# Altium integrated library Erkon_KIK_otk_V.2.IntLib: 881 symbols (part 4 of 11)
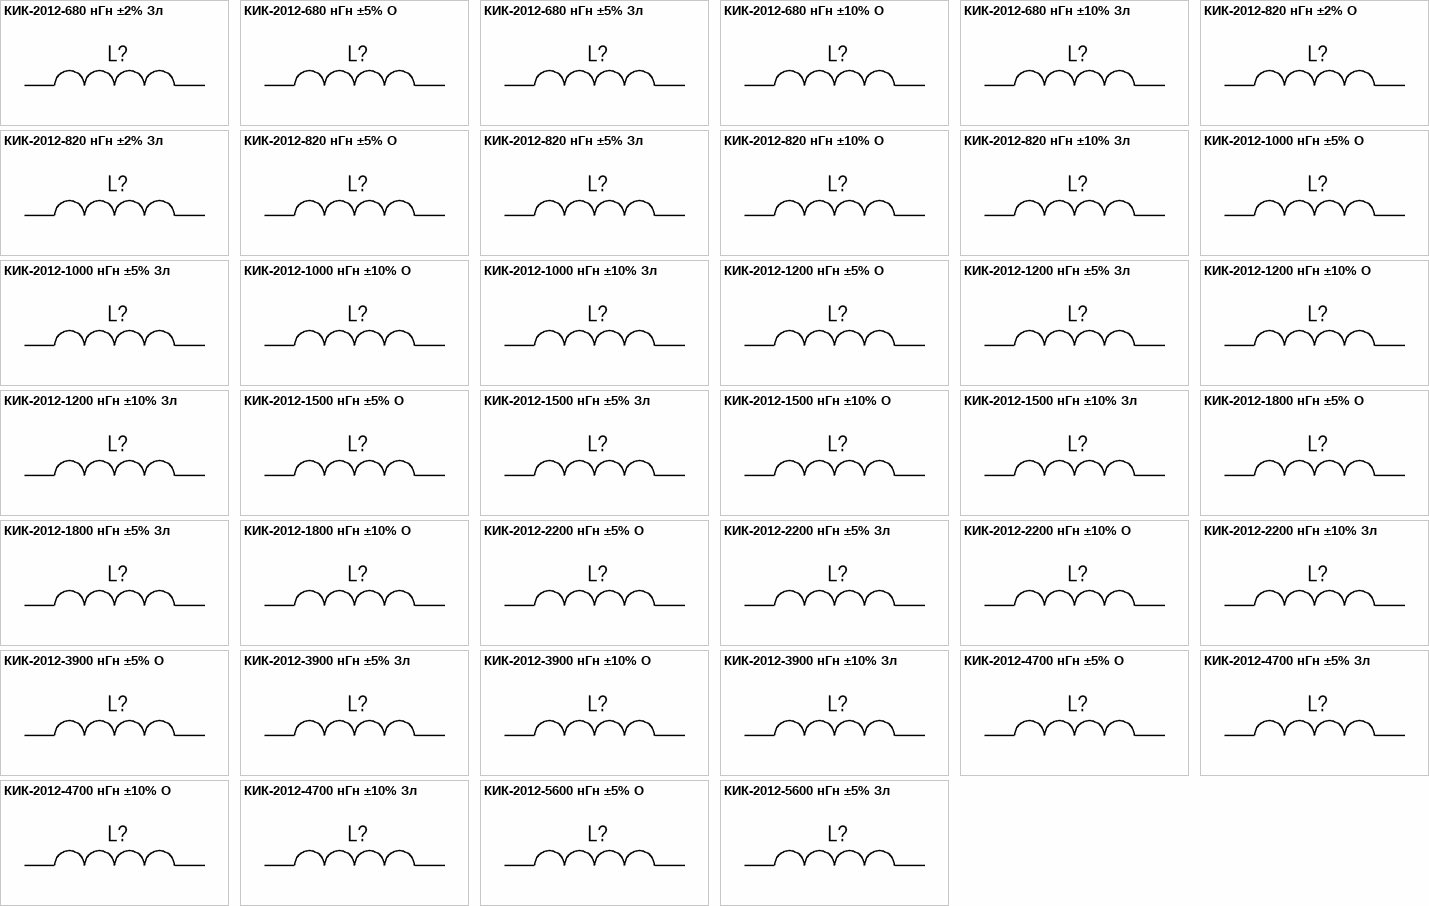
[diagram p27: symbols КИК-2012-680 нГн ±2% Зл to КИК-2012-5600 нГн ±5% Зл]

## КИК-2012-5600 нГн ±5% O
designator L?, comment 5600 нГн ±5%  (value not drawn)
Катушка индуктивности с керамическим сердечником и  финишным покрытием контактных площадок оловом; Добротность, не менее: 17; Резонансная частота, не менее: 0.065 ГГц; Сопротивление обмотки постоянноми току, не более: 7.8 Ом; Допустимый ток обмотки: 50 мА; Диапазон рабочих температур: от -60 до +125 ℃; Упаковка: Катушка и лента; Типоразмер: 2012 (0805); Технология монтажа: SMT; Изготовитель: АО "НПО "ЭРКОН"
footprint КИК-2012-O (Катушка индуктивности с керамическим сердечником типоразмер 2012(0805))
pins: 1, 2

## КИК-2012-5600 нГн ±5% Зл
designator L?, comment 5600 нГн ±5%  (value not drawn)
Катушка индуктивности с керамическим сердечником и золотым покрытием контактных площадок; Добротность, не менее: 17; Резонансная частота, не менее: 0.065 ГГц; Сопротивление обмотки постоянноми току, не более: 7.8 Ом; Допустимый ток обмотки: 50 мА; Диапазон рабочих температур: от -60 до +125 ℃; Упаковка: Катушка и лента; Типоразмер: 2012 (0805); Технология монтажа: SMT; Изготовитель: АО "НПО "ЭРКОН"
footprint КИК-2012-Зл (Катушка индуктивности с керамическим сердечникомтипоразмер 2012(0805))
pins: 1, 2

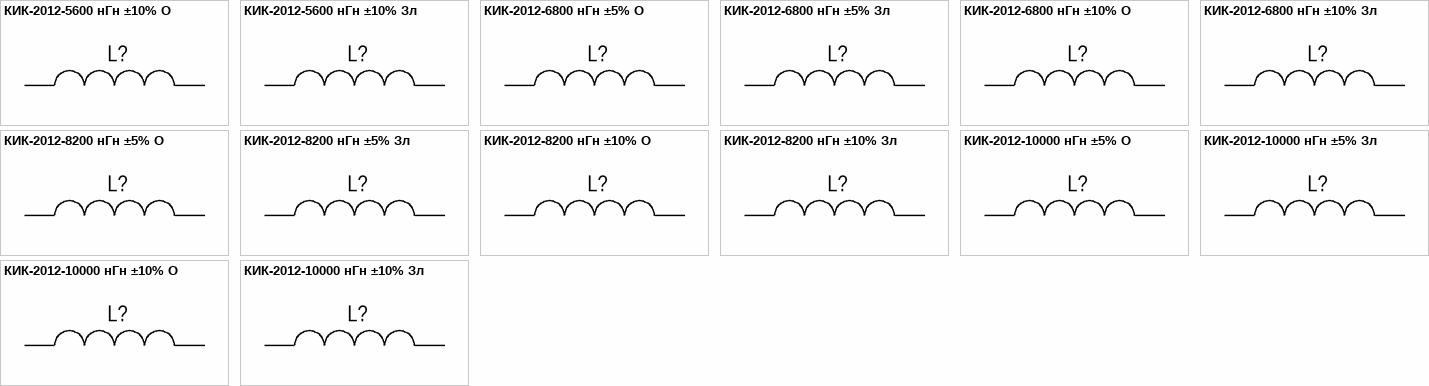
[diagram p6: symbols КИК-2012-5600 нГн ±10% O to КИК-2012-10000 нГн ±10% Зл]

## КИК-2012-5600 нГн ±10% O
designator L?, comment 5600 нГн ±10%  (value not drawn)
Катушка индуктивности с керамическим сердечником и  финишным покрытием контактных площадок оловом; Допускаемое отклонение индуктивности: ±5%; Добротность, не менее: 17; Резонансная частота, не менее: 0.065 ГГц; Сопротивление обмотки постоянноми току, не более: 7.8 Ом; Допустимый ток обмотки: 50 мА; Диапазон рабочих температур: от -60 до +125 ℃; Упаковка: Катушка и лента; Типоразмер: 2012 (0805); Технология монтажа: SMT; Изготовитель: АО "НПО "ЭРКОН"
footprint КИК-2012-O (Катушка индуктивности с керамическим сердечником типоразмер 2012(0805))
pins: 1, 2

## КИК-2012-5600 нГн ±10% Зл
designator L?, comment 5600 нГн ±10%  (value not drawn)
Катушка индуктивности с керамическим сердечником и золотым покрытием контактных площадок; Допускаемое отклонение индуктивности: ±5%; Добротность, не менее: 17; Резонансная частота, не менее: 0.065 ГГц; Сопротивление обмотки постоянноми току, не более: 7.8 Ом; Допустимый ток обмотки: 50 мА; Диапазон рабочих температур: от -60 до +125 ℃; Упаковка: Катушка и лента; Типоразмер: 2012 (0805); Технология монтажа: SMT; Изготовитель: АО "НПО "ЭРКОН"
footprint КИК-2012-Зл (Катушка индуктивности с керамическим сердечникомтипоразмер 2012(0805))
pins: 1, 2

## КИК-2012-6800 нГн ±5% O
designator L?, comment 6800 нГн ±5%  (value not drawn)
Катушка индуктивности с керамическим сердечником и  финишным покрытием контактных площадок оловом; Добротность, не менее: 17; Резонансная частота, не менее: 0.05 ГГц; Сопротивление обмотки постоянноми току, не более: 8.5 Ом; Допустимый ток обмотки: 45 мА; Диапазон рабочих температур: от -60 до +125 ℃; Упаковка: Катушка и лента; Типоразмер: 2012 (0805); Технология монтажа: SMT; Изготовитель: АО "НПО "ЭРКОН"
footprint КИК-2012-O (Катушка индуктивности с керамическим сердечником типоразмер 2012(0805))
pins: 1, 2

## КИК-2012-6800 нГн ±5% Зл
designator L?, comment 6800 нГн ±5%  (value not drawn)
Катушка индуктивности с керамическим сердечником и золотым покрытием контактных площадок; Добротность, не менее: 17; Резонансная частота, не менее: 0.05 ГГц; Сопротивление обмотки постоянноми току, не более: 8.5 Ом; Допустимый ток обмотки: 45 мА; Диапазон рабочих температур: от -60 до +125 ℃; Упаковка: Катушка и лента; Типоразмер: 2012 (0805); Технология монтажа: SMT; Изготовитель: АО "НПО "ЭРКОН"
footprint КИК-2012-Зл (Катушка индуктивности с керамическим сердечникомтипоразмер 2012(0805))
pins: 1, 2

## КИК-2012-6800 нГн ±10% O
designator L?, comment 6800 нГн ±10%  (value not drawn)
Катушка индуктивности с керамическим сердечником и  финишным покрытием контактных площадок оловом; Добротность, не менее: 17; Резонансная частота, не менее: 0.05 ГГц; Сопротивление обмотки постоянноми току, не более: 8.5 Ом; Допустимый ток обмотки: 45 мА; Диапазон рабочих температур: от -60 до +125 ℃; Упаковка: Катушка и лента; Типоразмер: 2012 (0805); Технология монтажа: SMT; Изготовитель: АО "НПО "ЭРКОН"
footprint КИК-2012-O (Катушка индуктивности с керамическим сердечником типоразмер 2012(0805))
pins: 1, 2

## КИК-2012-6800 нГн ±10% Зл
designator L?, comment 6800 нГн ±10%  (value not drawn)
Катушка индуктивности с керамическим сердечником и золотым покрытием контактных площадок; Добротность, не менее: 17; Резонансная частота, не менее: 0.05 ГГц; Сопротивление обмотки постоянноми току, не более: 8.5 Ом; Допустимый ток обмотки: 45 мА; Диапазон рабочих температур: от -60 до +125 ℃; Упаковка: Катушка и лента; Типоразмер: 2012 (0805); Технология монтажа: SMT; Изготовитель: АО "НПО "ЭРКОН"
footprint КИК-2012-Зл (Катушка индуктивности с керамическим сердечникомтипоразмер 2012(0805))
pins: 1, 2

## КИК-2012-8200 нГн ±5% O
designator L?, comment 8200 нГн ±5%  (value not drawn)
Катушка индуктивности с керамическим сердечником и  финишным покрытием контактных площадок оловом; Добротность, не менее: 17; Резонансная частота, не менее: 0.055 ГГц; Сопротивление обмотки постоянноми току, не более: 10.0 Ом; Допустимый ток обмотки: 40 мА; Диапазон рабочих температур: от -60 до +125 ℃; Упаковка: Катушка и лента; Типоразмер: 2012 (0805); Технология монтажа: SMT; Изготовитель: АО "НПО "ЭРКОН"
footprint КИК-2012-O (Катушка индуктивности с керамическим сердечником типоразмер 2012(0805))
pins: 1, 2

## КИК-2012-8200 нГн ±5% Зл
designator L?, comment 8200 нГн ±5%  (value not drawn)
Катушка индуктивности с керамическим сердечником и золотым покрытием контактных площадок; Добротность, не менее: 17; Резонансная частота, не менее: 0.055 ГГц; Сопротивление обмотки постоянноми току, не более: 10.0 Ом; Допустимый ток обмотки: 40 мА; Диапазон рабочих температур: от -60 до +125 ℃; Упаковка: Катушка и лента; Типоразмер: 2012 (0805); Технология монтажа: SMT; Изготовитель: АО "НПО "ЭРКОН"
footprint КИК-2012-Зл (Катушка индуктивности с керамическим сердечникомтипоразмер 2012(0805))
pins: 1, 2

## КИК-2012-8200 нГн ±10% O
designator L?, comment 8200 нГн ±10%  (value not drawn)
Катушка индуктивности с керамическим сердечником и  финишным покрытием контактных площадок оловом; Добротность, не менее: 17; Резонансная частота, не менее: 0.055 ГГц; Сопротивление обмотки постоянноми току, не более: 10.0 Ом; Допустимый ток обмотки: 40 мА; Диапазон рабочих температур: от -60 до +125 ℃; Упаковка: Катушка и лента; Типоразмер: 2012 (0805); Технология монтажа: SMT; Изготовитель: АО "НПО "ЭРКОН"
footprint КИК-2012-O (Катушка индуктивности с керамическим сердечником типоразмер 2012(0805))
pins: 1, 2

## КИК-2012-8200 нГн ±10% Зл
designator L?, comment 8200 нГн ±10%  (value not drawn)
Катушка индуктивности с керамическим сердечником и золотым покрытием контактных площадок; Добротность, не менее: 17; Резонансная частота, не менее: 0.055 ГГц; Сопротивление обмотки постоянноми току, не более: 10.0 Ом; Допустимый ток обмотки: 40 мА; Диапазон рабочих температур: от -60 до +125 ℃; Упаковка: Катушка и лента; Типоразмер: 2012 (0805); Технология монтажа: SMT; Изготовитель: АО "НПО "ЭРКОН"
footprint КИК-2012-Зл (Катушка индуктивности с керамическим сердечникомтипоразмер 2012(0805))
pins: 1, 2

## КИК-2012-10000 нГн ±5% O
designator L?, comment 10000 нГн ±5%  (value not drawn)
Катушка индуктивности с керамическим сердечником и  финишным покрытием контактных площадок оловом; Добротность, не менее: 17; Резонансная частота, не менее: 0.05 ГГц; Сопротивление обмотки постоянноми току, не более: 17.0 Ом; Допустимый ток обмотки: 40 мА; Диапазон рабочих температур: от -60 до +125 ℃; Упаковка: Катушка и лента; Типоразмер: 2012 (0805); Технология монтажа: SMT; Изготовитель: АО "НПО "ЭРКОН"
footprint КИК-2012-O (Катушка индуктивности с керамическим сердечником типоразмер 2012(0805))
pins: 1, 2

## КИК-2012-10000 нГн ±5% Зл
designator L?, comment 10000 нГн ±5%  (value not drawn)
Катушка индуктивности с керамическим сердечником и золотым покрытием контактных площадок; Добротность, не менее: 17; Резонансная частота, не менее: 0.05 ГГц; Сопротивление обмотки постоянноми току, не более: 17.0 Ом; Допустимый ток обмотки: 40 мА; Диапазон рабочих температур: от -60 до +125 ℃; Упаковка: Катушка и лента; Типоразмер: 2012 (0805); Технология монтажа: SMT; Изготовитель: АО "НПО "ЭРКОН"
footprint КИК-2012-Зл (Катушка индуктивности с керамическим сердечникомтипоразмер 2012(0805))
pins: 1, 2

## КИК-2012-10000 нГн ±10% O
designator L?, comment 10000 нГн ±10%  (value not drawn)
Катушка индуктивности с керамическим сердечником и  финишным покрытием контактных площадок оловом; Добротность, не менее: 17; Резонансная частота, не менее: 0.05 ГГц; Сопротивление обмотки постоянноми току, не более: 17.0 Ом; Допустимый ток обмотки: 40 мА; Диапазон рабочих температур: от -60 до +125 ℃; Упаковка: Катушка и лента; Типоразмер: 2012 (0805); Технология монтажа: SMT; Изготовитель: АО "НПО "ЭРКОН"
footprint КИК-2012-O (Катушка индуктивности с керамическим сердечником типоразмер 2012(0805))
pins: 1, 2

## КИК-2012-10000 нГн ±10% Зл
designator L?, comment 10000 нГн ±10%  (value not drawn)
Катушка индуктивности с керамическим сердечником и золотым покрытием контактных площадок; Добротность, не менее: 17; Резонансная частота, не менее: 0.05 ГГц; Сопротивление обмотки постоянноми току, не более: 17.0 Ом; Допустимый ток обмотки: 40 мА; Диапазон рабочих температур: от -60 до +125 ℃; Упаковка: Катушка и лента; Типоразмер: 2012 (0805); Технология монтажа: SMT; Изготовитель: АО "НПО "ЭРКОН"
footprint КИК-2012-Зл (Катушка индуктивности с керамическим сердечникомтипоразмер 2012(0805))
pins: 1, 2


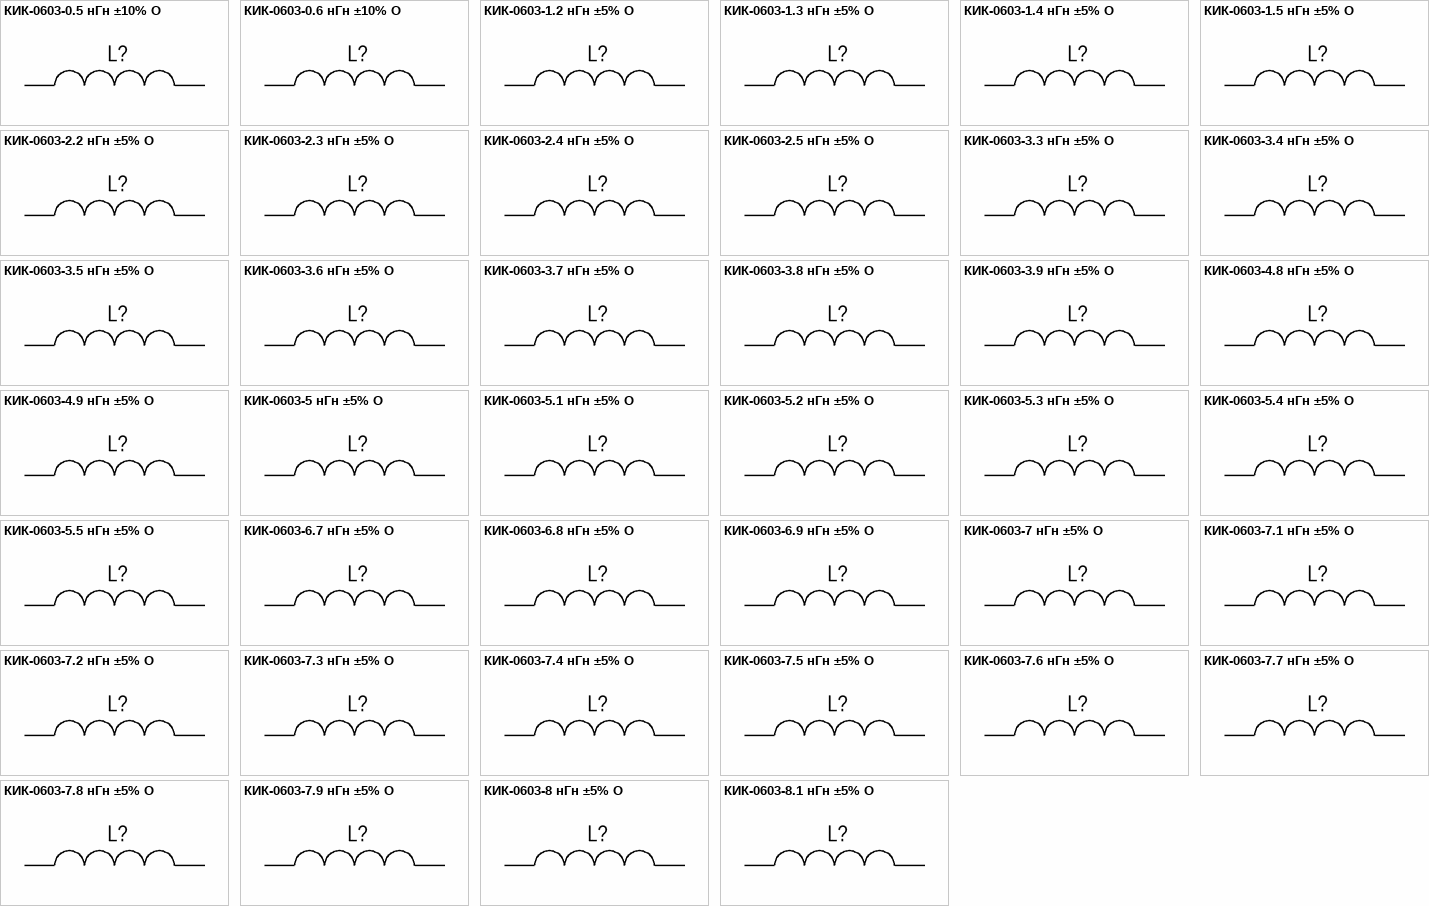
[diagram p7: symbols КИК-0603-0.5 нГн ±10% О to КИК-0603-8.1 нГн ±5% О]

## КИК-0603-0.5 нГн ±10% О
designator L?, comment 0.5нГн ±10%  (value not drawn)
Катушка индуктивности с керамическим сердечником; Добротность, не менее: 29; Резонансная частота, не менее: 23.5 ГГц; Сопротивление обмотки постоянноми току, не более: 0.02 Ом; Допустимый ток обмотки: 1250 мА; Диапазон рабочих температур: от -40 до +125 ℃; Упаковка: Катушка и лента; Типоразмер: 0603 (0201); Технология монтажа: SMT; Изготовитель: АО "НПО "ЭРКОН"
footprint КИК-0603_О (Катушка индуктивности с керамическим сердечником типоразмер 0603(0201))
pins: 1, 2

## КИК-0603-0.6 нГн ±10% О
designator L?, comment 0.6 нГн ±10%  (value not drawn)
Катушка индуктивности с керамическим сердечником; Номиналиная индуктивность: 0.6 нГн; Добротность, не менее: 31; Резонансная частота, не менее: 24.5 ГГц; Сопротивление обмотки постоянноми току, не более: 0.03 Ом; Допустимый ток обмотки: 1000 мА; Диапазон рабочих температур: от -40 до +125 ℃; Упаковка: Катушка и лента; Типоразмер: 0603 (0201); Технология монтажа: SMT; Изготовитель: АО "НПО "ЭРКОН"
footprint КИК-0603_О (Катушка индуктивности с керамическим сердечником типоразмер 0603(0201))
pins: 1, 2

## КИК-0603-1.2 нГн ±5% О
designator L?, comment 1.2 нГн ±5%  (value not drawn)
Катушка индуктивности с керамическим сердечником; Номиналиная индуктивность: 1.2 нГн; Добротность, не менее: 42; Резонансная частота, не менее: 17.9 ГГц; Сопротивление обмотки постоянноми току, не более: 0.042 Ом; Допустимый ток обмотки: 870 мА; Диапазон рабочих температур: от -40 до +125 ℃; Упаковка: Катушка и лента; Типоразмер: 0603 (0201); Технология монтажа: SMT; Изготовитель: АО "НПО "ЭРКОН"
footprint КИК-0603_О (Катушка индуктивности с керамическим сердечником типоразмер 0603(0201))
pins: 1, 2

## КИК-0603-1.3 нГн ±5% О
designator L?, comment 1.3 нГн ±5%  (value not drawn)
Катушка индуктивности с керамическим сердечником; Номиналиная индуктивность: 1.3 нГн; Добротность, не менее: 38; Резонансная частота, не менее: 17.6 ГГц; Сопротивление обмотки постоянноми току, не более: 0.048 Ом; Допустимый ток обмотки: 820 мА; Диапазон рабочих температур: от -40 до +125 ℃; Упаковка: Катушка и лента; Типоразмер: 0603 (0201); Технология монтажа: SMT; Изготовитель: АО "НПО "ЭРКОН"
footprint КИК-0603_О (Катушка индуктивности с керамическим сердечником типоразмер 0603(0201))
pins: 1, 2

## КИК-0603-1.4 нГн ±5% О
designator L?, comment 1.4 нГн ±5%  (value not drawn)
Катушка индуктивности с керамическим сердечником; Номиналиная индуктивность: 1.4 нГн; Добротность, не менее: 27; Резонансная частота, не менее: 17 ГГц; Сопротивление обмотки постоянноми току, не более: 0.08 Ом; Допустимый ток обмотки: 630 мА; Диапазон рабочих температур: от -40 до +125 ℃; Упаковка: Катушка и лента; Типоразмер: 0603 (0201); Технология монтажа: SMT; Изготовитель: АО "НПО "ЭРКОН"
footprint КИК-0603_О (Катушка индуктивности с керамическим сердечником типоразмер 0603(0201))
pins: 1, 2

## КИК-0603-1.5 нГн ±5% О
designator L?, comment 1.5 нГн ±5%  (value not drawn)
Катушка индуктивности с керамическим сердечником; Номиналиная индуктивность: 2.2 нГн; Добротность, не менее: 28; Резонансная частота, не менее: 17 ГГц; Сопротивление обмотки постоянноми току, не более: 0.09 Ом; Допустимый ток обмотки: 600 мА; Диапазон рабочих температур: от -40 до +125 ℃; Упаковка: Катушка и лента; Типоразмер: 0603 (0201); Технология монтажа: SMT; Изготовитель: АО "НПО "ЭРКОН"
footprint КИК-0603_О (Катушка индуктивности с керамическим сердечником типоразмер 0603(0201))
pins: 1, 2

## КИК-0603-2.2 нГн ±5% О
designator L?, comment 2.2 нГн ±5%  (value not drawn)
Катушка индуктивности с керамическим сердечником; Номиналиная индуктивность: 2.2 нГн; Добротность, не менее: 32; Резонансная частота, не менее: 16.7 ГГц; Сопротивление обмотки постоянноми току, не более: 0.07 Ом; Допустимый ток обмотки: 700 мА; Диапазон рабочих температур: от -40 до +125 ℃; Упаковка: Катушка и лента; Типоразмер: 0603 (0201); Технология монтажа: SMT; Изготовитель: АО "НПО "ЭРКОН"
footprint КИК-0603_О (Катушка индуктивности с керамическим сердечником типоразмер 0603(0201))
pins: 1, 2

## КИК-0603-2.3 нГн ±5% О
designator L?, comment 2.3 нГн ±5%  (value not drawn)
Катушка индуктивности с керамическим сердечником; Номиналиная индуктивность: 2.3 нГн; Добротность, не менее: 45; Резонансная частота, не менее: 16.5 ГГц; Сопротивление обмотки постоянноми току, не более: 0.07 Ом; Допустимый ток обмотки: 670 мА; Диапазон рабочих температур: от -40 до +125 ℃; Упаковка: Катушка и лента; Типоразмер: 0603 (0201); Технология монтажа: SMT; Изготовитель: АО "НПО "ЭРКОН"
footprint КИК-0603_О (Катушка индуктивности с керамическим сердечником типоразмер 0603(0201))
pins: 1, 2

## КИК-0603-2.4 нГн ±5% О
designator L?, comment 2.4 нГн ±5%  (value not drawn)
Катушка индуктивности с керамическим сердечником; Номиналиная индуктивность: 2.4 нГн; Добротность, не менее: 35; Резонансная частота, не менее: 13 ГГц; Сопротивление обмотки постоянноми току, не более: 0.082 Ом; Допустимый ток обмотки: 620 мА; Диапазон рабочих температур: от -40 до +125 ℃; Упаковка: Катушка и лента; Типоразмер: 0603 (0201); Технология монтажа: SMT; Изготовитель: АО "НПО "ЭРКОН"
footprint КИК-0603_О (Катушка индуктивности с керамическим сердечником типоразмер 0603(0201))
pins: 1, 2

## КИК-0603-2.5 нГн ±5% О
designator L?, comment 2.5 нГн ±5%  (value not drawn)
Катушка индуктивности с керамическим сердечником; Номиналиная индуктивность: 2.5 нГн; Добротность, не менее: 31; Резонансная частота, не менее: 12.5 ГГц; Сопротивление обмотки постоянноми току, не более: 0.165 Ом; Допустимый ток обмотки: 440 мА; Диапазон рабочих температур: от -40 до +125 ℃; Упаковка: Катушка и лента; Типоразмер: 0603 (0201); Технология монтажа: SMT; Изготовитель: АО "НПО "ЭРКОН"
footprint КИК-0603_О (Катушка индуктивности с керамическим сердечником типоразмер 0603(0201))
pins: 1, 2

## КИК-0603-3.3 нГн ±5% О
designator L?, comment 3.3 нГн ±5%  (value not drawn)
Катушка индуктивности с керамическим сердечником; Номиналиная индуктивность: 3.3 нГн; Добротность, не менее: 42; Резонансная частота, не менее: 12.8 ГГц; Сопротивление обмотки постоянноми току, не более: 0.08 Ом; Допустимый ток обмотки: 630 мА; Диапазон рабочих температур: от -40 до +125 ℃; Упаковка: Катушка и лента; Типоразмер: 0603 (0201); Технология монтажа: SMT; Изготовитель: АО "НПО "ЭРКОН"
footprint КИК-0603_О (Катушка индуктивности с керамическим сердечником типоразмер 0603(0201))
pins: 1, 2

## КИК-0603-3.4 нГн ±5% О
designator L?, comment 3.4 нГн ±5%  (value not drawn)
Катушка индуктивности с керамическим сердечником; Номиналиная индуктивность: 3.4 нГн; Добротность, не менее: 42; Резонансная частота, не менее: 12.7 ГГц; Сопротивление обмотки постоянноми току, не более: 0.08 Ом; Допустимый ток обмотки: 630 мА; Диапазон рабочих температур: от -40 до +125 ℃; Упаковка: Катушка и лента; Типоразмер: 0603 (0201); Технология монтажа: SMT; Изготовитель: АО "НПО "ЭРКОН"
footprint КИК-0603_О (Катушка индуктивности с керамическим сердечником типоразмер 0603(0201))
pins: 1, 2

## КИК-0603-3.5 нГн ±5% О
designator L?, comment 3.5 нГн ±5%  (value not drawn)
Катушка индуктивности с керамическим сердечником; Номиналиная индуктивность: 3.5 нГн; Добротность, не менее: 44; Резонансная частота, не менее: 12.4 ГГц; Сопротивление обмотки постоянноми току, не более: 0.08 Ом; Допустимый ток обмотки: 630 мА; Диапазон рабочих температур: от -40 до +125 ℃; Упаковка: Катушка и лента; Типоразмер: 0603 (0201); Технология монтажа: SMT; Изготовитель: АО "НПО "ЭРКОН"
footprint КИК-0603_О (Катушка индуктивности с керамическим сердечником типоразмер 0603(0201))
pins: 1, 2

## КИК-0603-3.6 нГн ±5% О
designator L?, comment 3.6 нГн ±5%  (value not drawn)
Катушка индуктивности с керамическим сердечником; Номиналиная индуктивность: 3.6 нГн; Добротность, не менее: 40; Резонансная частота, не менее: 12.5 ГГц; Сопротивление обмотки постоянноми току, не более: 0.105 Ом; Допустимый ток обмотки: 550 мА; Диапазон рабочих температур: от -40 до +125 ℃; Упаковка: Катушка и лента; Типоразмер: 0603 (0201); Технология монтажа: SMT; Изготовитель: АО "НПО "ЭРКОН"
footprint КИК-0603_О (Катушка индуктивности с керамическим сердечником типоразмер 0603(0201))
pins: 1, 2

## КИК-0603-3.7 нГн ±5% О
designator L?, comment 3.7 нГн ±5%  (value not drawn)
Катушка индуктивности с керамическим сердечником; Номиналиная индуктивность: 3.7 нГн; Добротность, не менее: 39; Резонансная частота, не менее: 10.6 ГГц; Сопротивление обмотки постоянноми току, не более: 0.105 Ом; Допустимый ток обмотки: 550 мА; Диапазон рабочих температур: от -40 до +125 ℃; Упаковка: Катушка и лента; Типоразмер: 0603 (0201); Технология монтажа: SMT; Изготовитель: АО "НПО "ЭРКОН"
footprint КИК-0603_О (Катушка индуктивности с керамическим сердечником типоразмер 0603(0201))
pins: 1, 2

## КИК-0603-3.8 нГн ±5% О
designator L?, comment 3.8 нГн ±5%  (value not drawn)
Катушка индуктивности с керамическим сердечником; Номиналиная индуктивность: 3.8 нГн; Добротность, не менее: 38; Резонансная частота, не менее: 10.2 ГГц; Сопротивление обмотки постоянноми току, не более: 0.18 Ом; Допустимый ток обмотки: 420 мА; Диапазон рабочих температур: от -40 до +125 ℃; Упаковка: Катушка и лента; Типоразмер: 0603 (0201); Технология монтажа: SMT; Изготовитель: АО "НПО "ЭРКОН"
footprint КИК-0603_О (Катушка индуктивности с керамическим сердечником типоразмер 0603(0201))
pins: 1, 2

## КИК-0603-3.9 нГн ±5% О
designator L?, comment 3.9 нГн ±5%  (value not drawn)
Катушка индуктивности с керамическим сердечником; Номиналиная индуктивность: 3.9 нГн; Добротность, не менее: 35; Резонансная частота, не менее: 11.2 ГГц; Сопротивление обмотки постоянноми току, не более: 0.24 Ом; Допустимый ток обмотки: 360 мА; Диапазон рабочих температур: от -40 до +125 ℃; Упаковка: Катушка и лента; Типоразмер: 0603 (0201); Технология монтажа: SMT; Изготовитель: АО "НПО "ЭРКОН"
footprint КИК-0603_О (Катушка индуктивности с керамическим сердечником типоразмер 0603(0201))
pins: 1, 2

## КИК-0603-4.8 нГн ±5% О
designator L?, comment 4.8 нГн ±5%  (value not drawn)
Катушка индуктивности с керамическим сердечником; Номиналиная индуктивность: 4.8 нГн; Добротность, не менее: 34; Резонансная частота, не менее: 11 ГГц; Сопротивление обмотки постоянноми току, не более: 0.096 Ом; Допустимый ток обмотки: 570 мА; Диапазон рабочих температур: от -40 до +125 ℃; Упаковка: Катушка и лента; Типоразмер: 0603 (0201); Технология монтажа: SMT; Изготовитель: АО "НПО "ЭРКОН"
footprint КИК-0603_О (Катушка индуктивности с керамическим сердечником типоразмер 0603(0201))
pins: 1, 2

## КИК-0603-4.9 нГн ±5% О
designator L?, comment 4.9 нГн ±5%  (value not drawn)
Катушка индуктивности с керамическим сердечником; Номиналиная индуктивность: 4.9 нГн; Добротность, не менее: 33; Резонансная частота, не менее: 11.7 ГГц; Сопротивление обмотки постоянноми току, не более: 0.13 Ом; Допустимый ток обмотки: 510 мА; Диапазон рабочих температур: от -40 до +125 ℃; Упаковка: Катушка и лента; Типоразмер: 0603 (0201); Технология монтажа: SMT; Изготовитель: АО "НПО "ЭРКОН"
footprint КИК-0603_О (Катушка индуктивности с керамическим сердечником типоразмер 0603(0201))
pins: 1, 2

## КИК-0603-5 нГн ±5% О
designator L?, comment 5 нГн ±5%  (value not drawn)
Катушка индуктивности с керамическим сердечником; Номиналиная индуктивность: 5 нГн; Добротность, не менее: 34; Резонансная частота, не менее: 11.5 ГГц; Сопротивление обмотки постоянноми току, не более: 0.13 Ом; Допустимый ток обмотки: 510 мА; Диапазон рабочих температур: от -40 до +125 ℃; Упаковка: Катушка и лента; Типоразмер: 0603 (0201); Технология монтажа: SMT; Изготовитель: АО "НПО "ЭРКОН"
footprint КИК-0603_О (Катушка индуктивности с керамическим сердечником типоразмер 0603(0201))
pins: 1, 2

## КИК-0603-5.1 нГн ±5% О
designator L?, comment 5.1 нГн ±5%  (value not drawn)
Катушка индуктивности с керамическим сердечником; Номиналиная индуктивность: 5.1 нГн; Добротность, не менее: 35; Резонансная частота, не менее: 11.1 ГГц; Сопротивление обмотки постоянноми току, не более: 0.13 Ом; Допустимый ток обмотки: 510 мА; Диапазон рабочих температур: от -40 до +125 ℃; Упаковка: Катушка и лента; Типоразмер: 0603 (0201); Технология монтажа: SMT; Изготовитель: АО "НПО "ЭРКОН"
footprint КИК-0603_О (Катушка индуктивности с керамическим сердечником типоразмер 0603(0201))
pins: 1, 2

## КИК-0603-5.2 нГн ±5% О
designator L?, comment 5.2 нГн ±5%  (value not drawn)
Катушка индуктивности с керамическим сердечником; Номиналиная индуктивность: 5.2 нГн; Добротность, не менее: 36; Резонансная частота, не менее: 10 ГГц; Сопротивление обмотки постоянноми току, не более: 0.17 Ом; Допустимый ток обмотки: 430 мА; Диапазон рабочих температур: от -40 до +125 ℃; Упаковка: Катушка и лента; Типоразмер: 0603 (0201); Технология монтажа: SMT; Изготовитель: АО "НПО "ЭРКОН"
footprint КИК-0603_О (Катушка индуктивности с керамическим сердечником типоразмер 0603(0201))
pins: 1, 2

## КИК-0603-5.3 нГн ±5% О
designator L?, comment 5.3 нГн ±5%  (value not drawn)
Катушка индуктивности с керамическим сердечником; Номиналиная индуктивность: 5.3 нГн; Добротность, не менее: 36; Резонансная частота, не менее: 10.6 ГГц; Сопротивление обмотки постоянноми току, не более: 0.13 Ом; Допустимый ток обмотки: 510 мА; Диапазон рабочих температур: от -40 до +125 ℃; Упаковка: Катушка и лента; Типоразмер: 0603 (0201); Технология монтажа: SMT; Изготовитель: АО "НПО "ЭРКОН"
footprint КИК-0603_О (Катушка индуктивности с керамическим сердечником типоразмер 0603(0201))
pins: 1, 2

## КИК-0603-5.4 нГн ±5% О
designator L?, comment 5.4 нГн ±5%  (value not drawn)
Катушка индуктивности с керамическим сердечником; Номиналиная индуктивность: 5.4 нГн; Добротность, не менее: 36; Резонансная частота, не менее: 10.2 ГГц; Сопротивление обмотки постоянноми току, не более: 0.13 Ом; Допустимый ток обмотки: 510 мА; Диапазон рабочих температур: от -40 до +125 ℃; Упаковка: Катушка и лента; Типоразмер: 0603 (0201); Технология монтажа: SMT; Изготовитель: АО "НПО "ЭРКОН"
footprint КИК-0603_О (Катушка индуктивности с керамическим сердечником типоразмер 0603(0201))
pins: 1, 2

## КИК-0603-5.5 нГн ±5% О
designator L?, comment 5.5 нГн ±5%  (value not drawn)
Катушка индуктивности с керамическим сердечником; Номиналиная индуктивность: 5.5 нГн; Добротность, не менее: 35; Резонансная частота, не менее: 9.5 ГГц; Сопротивление обмотки постоянноми току, не более: 0.285 Ом; Допустимый ток обмотки: 330 мА; Диапазон рабочих температур: от -40 до +125 ℃; Упаковка: Катушка и лента; Типоразмер: 0603 (0201); Технология монтажа: SMT; Изготовитель: АО "НПО "ЭРКОН"
footprint КИК-0603_О (Катушка индуктивности с керамическим сердечником типоразмер 0603(0201))
pins: 1, 2

## КИК-0603-6.7 нГн ±5% О
designator L?, comment 6.7 нГн ±5%  (value not drawn)
Катушка индуктивности с керамическим сердечником; Номиналиная индуктивность: 6.7 нГн; Добротность, не менее: 40; Резонансная частота, не менее: 6.8 ГГц; Сопротивление обмотки постоянноми току, не более: 0.15 Ом; Допустимый ток обмотки: 460 мА; Диапазон рабочих температур: от -40 до +125 ℃; Упаковка: Катушка и лента; Типоразмер: 0603 (0201); Технология монтажа: SMT; Изготовитель: АО "НПО "ЭРКОН"
footprint КИК-0603_О (Катушка индуктивности с керамическим сердечником типоразмер 0603(0201))
pins: 1, 2

## КИК-0603-6.8 нГн ±5% О
designator L?, comment 6.8 нГн ±5%  (value not drawn)
Катушка индуктивности с керамическим сердечником; Номиналиная индуктивность: 6.8 нГн; Добротность, не менее: 35; Резонансная частота, не менее: 9.5 ГГц; Сопротивление обмотки постоянноми току, не более: 0.15 Ом; Допустимый ток обмотки: 460 мА; Диапазон рабочих температур: от -40 до +125 ℃; Упаковка: Катушка и лента; Типоразмер: 0603 (0201); Технология монтажа: SMT; Изготовитель: АО "НПО "ЭРКОН"
footprint КИК-0603_О (Катушка индуктивности с керамическим сердечником типоразмер 0603(0201))
pins: 1, 2

## КИК-0603-6.9 нГн ±5% О
designator L?, comment 6.9 нГн ±5%  (value not drawn)
Катушка индуктивности с керамическим сердечником; Номиналиная индуктивность: 6.9 нГн; Добротность, не менее: 36; Резонансная частота, не менее: 9.3 ГГц; Сопротивление обмотки постоянноми току, не более: 0.15 Ом; Допустимый ток обмотки: 460 мА; Диапазон рабочих температур: от -40 до +125 ℃; Упаковка: Катушка и лента; Типоразмер: 0603 (0201); Технология монтажа: SMT; Изготовитель: АО "НПО "ЭРКОН"
footprint КИК-0603_О (Катушка индуктивности с керамическим сердечником типоразмер 0603(0201))
pins: 1, 2

## КИК-0603-7 нГн ±5% О
designator L?, comment 7 нГн ±5%  (value not drawn)
Катушка индуктивности с керамическим сердечником; Номиналиная индуктивность: 7 нГн; Добротность, не менее: 39; Резонансная частота, не менее: 6.7 ГГц; Сопротивление обмотки постоянноми току, не более: 0.21 Ом; Допустимый ток обмотки: 390 мА; Диапазон рабочих температур: от -40 до +125 ℃; Упаковка: Катушка и лента; Типоразмер: 0603 (0201); Технология монтажа: SMT; Изготовитель: АО "НПО "ЭРКОН"
footprint КИК-0603_О (Катушка индуктивности с керамическим сердечником типоразмер 0603(0201))
pins: 1, 2

## КИК-0603-7.1 нГн ±5% О
designator L?, comment 7.1 нГн ±5%  (value not drawn)
Катушка индуктивности с керамическим сердечником; Номиналиная индуктивность: 7.1 нГн; Добротность, не менее: 36; Резонансная частота, не менее: 9.5 ГГц; Сопротивление обмотки постоянноми току, не более: 0.25 Ом; Допустимый ток обмотки: 390 мА; Диапазон рабочих температур: от -40 до +125 ℃; Упаковка: Катушка и лента; Типоразмер: 0603 (0201); Технология монтажа: SMT; Изготовитель: АО "НПО "ЭРКОН"
footprint КИК-0603_О (Катушка индуктивности с керамическим сердечником типоразмер 0603(0201))
pins: 1, 2

## КИК-0603-7.2 нГн ±5% О
designator L?, comment 7.2 нГн ±5%  (value not drawn)
Катушка индуктивности с керамическим сердечником; Номиналиная индуктивность: 7.2 нГн; Добротность, не менее: 36; Резонансная частота, не менее: 9.4 ГГц; Сопротивление обмотки постоянноми току, не более: 0.25 Ом; Допустимый ток обмотки: 390 мА; Диапазон рабочих температур: от -40 до +125 ℃; Упаковка: Катушка и лента; Типоразмер: 0603 (0201); Технология монтажа: SMT; Изготовитель: АО "НПО "ЭРКОН"
footprint КИК-0603_О (Катушка индуктивности с керамическим сердечником типоразмер 0603(0201))
pins: 1, 2

## КИК-0603-7.3 нГн ±5% О
designator L?, comment 7.3 нГн ±5%  (value not drawn)
Катушка индуктивности с керамическим сердечником; Номиналиная индуктивность: 7.3 нГн; Добротность, не менее: 37; Резонансная частота, не менее: 9.3 ГГц; Сопротивление обмотки постоянноми току, не более: 0.25 Ом; Допустимый ток обмотки: 390 мА; Диапазон рабочих температур: от -40 до +125 ℃; Упаковка: Катушка и лента; Типоразмер: 0603 (0201); Технология монтажа: SMT; Изготовитель: АО "НПО "ЭРКОН"
footprint КИК-0603_О (Катушка индуктивности с керамическим сердечником типоразмер 0603(0201))
pins: 1, 2

## КИК-0603-7.4 нГн ±5% О
designator L?, comment 7.4 нГн ±5%  (value not drawn)
Катушка индуктивности с керамическим сердечником; Номиналиная индуктивность: 7.4 нГн; Добротность, не менее: 40; Резонансная частота, не менее: 9.1 ГГц; Сопротивление обмотки постоянноми току, не более: 0.25 Ом; Допустимый ток обмотки: 390 мА; Диапазон рабочих температур: от -40 до +125 ℃; Упаковка: Катушка и лента; Типоразмер: 0603 (0201); Технология монтажа: SMT; Изготовитель: АО "НПО "ЭРКОН"
footprint КИК-0603_О (Катушка индуктивности с керамическим сердечником типоразмер 0603(0201))
pins: 1, 2

## КИК-0603-7.5 нГн ±5% О
designator L?, comment 7.5 нГн ±5%  (value not drawn)
Катушка индуктивности с керамическим сердечником; Номиналиная индуктивность: 7.5 нГн; Добротность, не менее: 36; Резонансная частота, не менее: 6.8 ГГц; Сопротивление обмотки постоянноми току, не более: 0.34 Ом; Допустимый ток обмотки: 300 мА; Диапазон рабочих температур: от -40 до +125 ℃; Упаковка: Катушка и лента; Типоразмер: 0603 (0201); Технология монтажа: SMT; Изготовитель: АО "НПО "ЭРКОН"
footprint КИК-0603_О (Катушка индуктивности с керамическим сердечником типоразмер 0603(0201))
pins: 1, 2

## КИК-0603-7.6 нГн ±5% О
designator L?, comment 7.6 нГн ±5%  (value not drawn)
Катушка индуктивности с керамическим сердечником; Номиналиная индуктивность: 7.6 нГн; Добротность, не менее: 39; Резонансная частота, не менее: 9.3 ГГц; Сопротивление обмотки постоянноми току, не более: 0.30 Ом; Допустимый ток обмотки: 340 мА; Диапазон рабочих температур: от -40 до +125 ℃; Упаковка: Катушка и лента; Типоразмер: 0603 (0201); Технология монтажа: SMT; Изготовитель: АО "НПО "ЭРКОН"
footprint КИК-0603_О (Катушка индуктивности с керамическим сердечником типоразмер 0603(0201))
pins: 1, 2

## КИК-0603-7.7 нГн ±5% О
designator L?, comment 7.7 нГн ±5%  (value not drawn)
Катушка индуктивности с керамическим сердечником; Номиналиная индуктивность: 7.7 нГн; Добротность, не менее: 39; Резонансная частота, не менее: 9.2 ГГц; Сопротивление обмотки постоянноми току, не более: 0.30 Ом; Допустимый ток обмотки: 340 мА; Диапазон рабочих температур: от -40 до +125 ℃; Упаковка: Катушка и лента; Типоразмер: 0603 (0201); Технология монтажа: SMT; Изготовитель: АО "НПО "ЭРКОН"
footprint КИК-0603_О (Катушка индуктивности с керамическим сердечником типоразмер 0603(0201))
pins: 1, 2

## КИК-0603-7.8 нГн ±5% О
designator L?, comment 7.8 нГн ±5%  (value not drawn)
Катушка индуктивности с керамическим сердечником; Номиналиная индуктивность: 7.8 нГн; Добротность, не менее: 38; Резонансная частота, не менее: 9.2 ГГц; Сопротивление обмотки постоянноми току, не более: 0.30 Ом; Допустимый ток обмотки: 340 мА; Диапазон рабочих температур: от -40 до +125 ℃; Упаковка: Катушка и лента; Типоразмер: 0603 (0201); Технология монтажа: SMT; Изготовитель: АО "НПО "ЭРКОН"
footprint КИК-0603_О (Катушка индуктивности с керамическим сердечником типоразмер 0603(0201))
pins: 1, 2

## КИК-0603-7.9 нГн ±5% О
designator L?, comment 7.9 нГн ±5%  (value not drawn)
Катушка индуктивности с керамическим сердечником; Номиналиная индуктивность: 7.9 нГн; Добротность, не менее: 38; Резонансная частота, не менее: 9.1 ГГц; Сопротивление обмотки постоянноми току, не более: 0.30 Ом; Допустимый ток обмотки: 340 мА; Диапазон рабочих температур: от -40 до +125 ℃; Упаковка: Катушка и лента; Типоразмер: 0603 (0201); Технология монтажа: SMT; Изготовитель: АО "НПО "ЭРКОН"
footprint КИК-0603_О (Катушка индуктивности с керамическим сердечником типоразмер 0603(0201))
pins: 1, 2

## КИК-0603-8 нГн ±5% О
designator L?, comment 8 нГн ±5%  (value not drawn)
Катушка индуктивности с керамическим сердечником; Номиналиная индуктивность: 8 нГн; Добротность, не менее: 35; Резонансная частота, не менее: 9.2 ГГц; Сопротивление обмотки постоянноми току, не более: 0.30 Ом; Допустимый ток обмотки: 340 мА; Диапазон рабочих температур: от -40 до +125 ℃; Упаковка: Катушка и лента; Типоразмер: 0603 (0201); Технология монтажа: SMT; Изготовитель: АО "НПО "ЭРКОН"
footprint КИК-0603_О (Катушка индуктивности с керамическим сердечником типоразмер 0603(0201))
pins: 1, 2

## КИК-0603-8.1 нГн ±5% О
designator L?, comment 8.1 нГн ±5%  (value not drawn)
Катушка индуктивности с керамическим сердечником; Номиналиная индуктивность: 8.1 нГн; Добротность, не менее: 37; Резонансная частота, не менее: 9.1 ГГц; Сопротивление обмотки постоянноми току, не более: 0.30 Ом; Допустимый ток обмотки: 340 мА; Диапазон рабочих температур: от -40 до +125 ℃; Упаковка: Катушка и лента; Типоразмер: 0603 (0201); Технология монтажа: SMT; Изготовитель: АО "НПО "ЭРКОН"
footprint КИК-0603_О (Катушка индуктивности с керамическим сердечником типоразмер 0603(0201))
pins: 1, 2

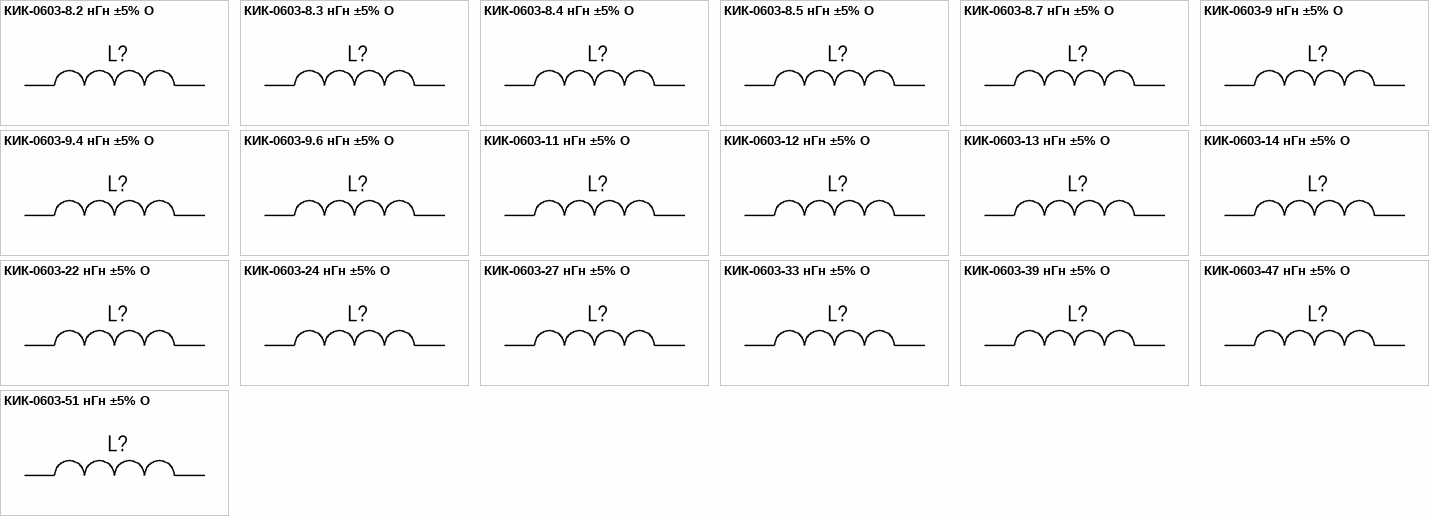
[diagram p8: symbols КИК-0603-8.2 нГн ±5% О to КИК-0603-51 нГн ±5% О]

## КИК-0603-8.2 нГн ±5% О
designator L?, comment 8.2 нГн ±5%  (value not drawn)
Катушка индуктивности с керамическим сердечником; Номиналиная индуктивность: 8.2 нГн; Добротность, не менее: 37; Резонансная частота, не менее: 6.4 ГГц; Сопротивление обмотки постоянноми току, не более: 0.27 Ом; Допустимый ток обмотки: 340 мА; Диапазон рабочих температур: от -40 до +125 ℃; Упаковка: Катушка и лента; Типоразмер: 0603 (0201); Технология монтажа: SMT; Изготовитель: АО "НПО "ЭРКОН"
footprint КИК-0603_О (Катушка индуктивности с керамическим сердечником типоразмер 0603(0201))
pins: 1, 2

## КИК-0603-8.3 нГн ±5% О
designator L?, comment 8.3 нГн ±5%  (value not drawn)
Катушка индуктивности с керамическим сердечником; Номиналиная индуктивность: 8.3 нГн; Добротность, не менее: 36; Резонансная частота, не менее: 8.9 ГГц; Сопротивление обмотки постоянноми току, не более: 0.3 Ом; Допустимый ток обмотки: 340 мА; Диапазон рабочих температур: от -40 до +125 ℃; Упаковка: Катушка и лента; Типоразмер: 0603 (0201); Технология монтажа: SMT; Изготовитель: АО "НПО "ЭРКОН"
footprint КИК-0603_О (Катушка индуктивности с керамическим сердечником типоразмер 0603(0201))
pins: 1, 2

## КИК-0603-8.4 нГн ±5% О
designator L?, comment 8.4 нГн ±5%  (value not drawn)
Катушка индуктивности с керамическим сердечником; Номиналиная индуктивность: 8.4 нГн; Добротность, не менее: 35; Резонансная частота, не менее: 8.9 ГГц; Сопротивление обмотки постоянноми току, не более: 0.35 Ом; Допустимый ток обмотки: 300 мА; Диапазон рабочих температур: от -40 до +125 ℃; Упаковка: Катушка и лента; Типоразмер: 0603 (0201); Технология монтажа: SMT; Изготовитель: АО "НПО "ЭРКОН"
footprint КИК-0603_О (Катушка индуктивности с керамическим сердечником типоразмер 0603(0201))
pins: 1, 2

## КИК-0603-8.5 нГн ±5% О
designator L?, comment 8.5 нГн ±5%  (value not drawn)
Катушка индуктивности с керамическим сердечником; Номиналиная индуктивность: 8.5 нГн; Добротность, не менее: 35; Резонансная частота, не менее: 8.9 ГГц; Сопротивление обмотки постоянноми току, не более: 0.35 Ом; Допустимый ток обмотки: 300 мА; Диапазон рабочих температур: от -40 до +125 ℃; Упаковка: Катушка и лента; Типоразмер: 0603 (0201); Технология монтажа: SMT; Изготовитель: АО "НПО "ЭРКОН"
footprint КИК-0603_О (Катушка индуктивности с керамическим сердечником типоразмер 0603(0201))
pins: 1, 2

## КИК-0603-8.7 нГн ±5% О
designator L?, comment 8.7 нГн ±5%  (value not drawn)
Катушка индуктивности с керамическим сердечником; Номиналиная индуктивность: 8.7 нГн; Добротность, не менее: 38; Резонансная частота, не менее: 6.3 ГГц; Сопротивление обмотки постоянноми току, не более: 0.35 Ом; Допустимый ток обмотки: 300 мА; Диапазон рабочих температур: от -40 до +125 ℃; Упаковка: Катушка и лента; Типоразмер: 0603 (0201); Технология монтажа: SMT; Изготовитель: АО "НПО "ЭРКОН"
footprint КИК-0603_О (Катушка индуктивности с керамическим сердечником типоразмер 0603(0201))
pins: 1, 2

## КИК-0603-9 нГн ±5% О
designator L?, comment 9 нГн ±5%  (value not drawn)
Катушка индуктивности с керамическим сердечником; Номиналиная индуктивность: 9 нГн; Добротность, не менее: 42; Резонансная частота, не менее: 6.4 ГГц; Сопротивление обмотки постоянноми току, не более: 0.35 Ом; Допустимый ток обмотки: 300 мА; Диапазон рабочих температур: от -40 до +125 ℃; Упаковка: Катушка и лента; Типоразмер: 0603 (0201); Технология монтажа: SMT; Изготовитель: АО "НПО "ЭРКОН"
footprint КИК-0603_О (Катушка индуктивности с керамическим сердечником типоразмер 0603(0201))
pins: 1, 2

## КИК-0603-9.4 нГн ±5% О
designator L?, comment 9.4 нГн ±5%  (value not drawn)
Катушка индуктивности с керамическим сердечником; Номиналиная индуктивность: 9.4 нГн; Добротность, не менее: 36; Резонансная частота, не менее: 6.4 ГГц; Сопротивление обмотки постоянноми току, не более: 0.4 Ом; Допустимый ток обмотки: 280 мА; Диапазон рабочих температур: от -40 до +125 ℃; Упаковка: Катушка и лента; Типоразмер: 0603 (0201); Технология монтажа: SMT; Изготовитель: АО "НПО "ЭРКОН"
footprint КИК-0603_О (Катушка индуктивности с керамическим сердечником типоразмер 0603(0201))
pins: 1, 2

## КИК-0603-9.6 нГн ±5% О
designator L?, comment 9.6 нГн ±5%  (value not drawn)
Катушка индуктивности с керамическим сердечником; Номиналиная индуктивность: 9.6 нГн; Добротность, не менее: 38; Резонансная частота, не менее: 6.2 ГГц; Сопротивление обмотки постоянноми току, не более: 0.4 Ом; Допустимый ток обмотки: 280 мА; Диапазон рабочих температур: от -40 до +125 ℃; Упаковка: Катушка и лента; Типоразмер: 0603 (0201); Технология монтажа: SMT; Изготовитель: АО "НПО "ЭРКОН"
footprint КИК-0603_О (Катушка индуктивности с керамическим сердечником типоразмер 0603(0201))
pins: 1, 2

## КИК-0603-11 нГн ±5% О
designator L?, comment 11 нГн ±5%  (value not drawn)
Катушка индуктивности с керамическим сердечником; Номиналиная индуктивность: 11 нГн; Добротность, не менее: 40; Резонансная частота, не менее: 5.7 ГГц; Сопротивление обмотки постоянноми току, не более: 0.4 Ом; Допустимый ток обмотки: 280 мА; Диапазон рабочих температур: от -40 до +125 ℃; Упаковка: Катушка и лента; Типоразмер: 0603 (0201); Технология монтажа: SMT; Изготовитель: АО "НПО "ЭРКОН"
footprint КИК-0603_О (Катушка индуктивности с керамическим сердечником типоразмер 0603(0201))
pins: 1, 2

## КИК-0603-12 нГн ±5% О
designator L?, comment 12 нГн ±5%  (value not drawn)
Катушка индуктивности с керамическим сердечником; Номиналиная индуктивность: 12 нГн; Добротность, не менее: 39; Резонансная частота, не менее: 5.6 ГГц; Сопротивление обмотки постоянноми току, не более: 0.36 Ом; Допустимый ток обмотки: 300 мА; Диапазон рабочих температур: от -40 до +125 ℃; Упаковка: Катушка и лента; Типоразмер: 0603 (0201); Технология монтажа: SMT; Изготовитель: АО "НПО "ЭРКОН"
footprint КИК-0603_О (Катушка индуктивности с керамическим сердечником типоразмер 0603(0201))
pins: 1, 2

## КИК-0603-13 нГн ±5% О
designator L?, comment 13 нГн ±5%  (value not drawn)
Катушка индуктивности с керамическим сердечником; Номиналиная индуктивность: 13 нГн; Добротность, не менее: 38; Резонансная частота, не менее: 6.7 ГГц; Сопротивление обмотки постоянноми току, не более: 0.44 Ом; Допустимый ток обмотки: 270 мА; Диапазон рабочих температур: от -40 до +125 ℃; Упаковка: Катушка и лента; Типоразмер: 0603 (0201); Технология монтажа: SMT; Изготовитель: АО "НПО "ЭРКОН"
footprint КИК-0603_О (Катушка индуктивности с керамическим сердечником типоразмер 0603(0201))
pins: 1, 2

## КИК-0603-14 нГн ±5% О
designator L?, comment 14 нГн ±5%  (value not drawn)
Катушка индуктивности с керамическим сердечником; Номиналиная индуктивность: 14 нГн; Добротность, не менее: 37; Резонансная частота, не менее: 5.1 ГГц; Сопротивление обмотки постоянноми току, не более: 0.44 Ом; Допустимый ток обмотки: 270 мА; Диапазон рабочих температур: от -40 до +125 ℃; Упаковка: Катушка и лента; Типоразмер: 0603 (0201); Технология монтажа: SMT; Изготовитель: АО "НПО "ЭРКОН"
footprint КИК-0603_О (Катушка индуктивности с керамическим сердечником типоразмер 0603(0201))
pins: 1, 2

## КИК-0603-22 нГн ±5% О
designator L?, comment 22 нГн ±5%  (value not drawn)
Катушка индуктивности с керамическим сердечником; Номиналиная индуктивность: 22 нГн; Добротность, не менее: 36; Резонансная частота, не менее: 4.35 ГГц; Сопротивление обмотки постоянноми току, не более: 0.75 Ом; Допустимый ток обмотки: 140 мА; Диапазон рабочих температур: от -40 до +125 ℃; Упаковка: Катушка и лента; Типоразмер: 0603 (0201); Технология монтажа: SMT; Изготовитель: АО "НПО "ЭРКОН"
footprint КИК-0603_О (Катушка индуктивности с керамическим сердечником типоразмер 0603(0201))
pins: 1, 2

## КИК-0603-24 нГн ±5% О
designator L?, comment 24 нГн ±5%  (value not drawn)
Катушка индуктивности с керамическим сердечником; Номиналиная индуктивность: 24 нГн; Добротность, не менее: 36; Резонансная частота, не менее: 4.35 ГГц; Сопротивление обмотки постоянноми току, не более: 0.93 Ом; Допустимый ток обмотки: 130 мА; Диапазон рабочих температур: от -40 до +125 ℃; Упаковка: Катушка и лента; Типоразмер: 0603 (0201); Технология монтажа: SMT; Изготовитель: АО "НПО "ЭРКОН"
footprint КИК-0603_О (Катушка индуктивности с керамическим сердечником типоразмер 0603(0201))
pins: 1, 2

## КИК-0603-27 нГн ±5% О
designator L?, comment 27 нГн ±5%  (value not drawn)
Катушка индуктивности с керамическим сердечником; Номиналиная индуктивность: 27 нГн; Добротность, не менее: 35; Резонансная частота, не менее: 3.95 ГГц; Сопротивление обмотки постоянноми току, не более: 1.03 Ом; Допустимый ток обмотки: 125 мА; Диапазон рабочих температур: от -40 до +125 ℃; Упаковка: Катушка и лента; Типоразмер: 0603 (0201); Технология монтажа: SMT; Изготовитель: АО "НПО "ЭРКОН"
footprint КИК-0603_О (Катушка индуктивности с керамическим сердечником типоразмер 0603(0201))
pins: 1, 2

## КИК-0603-33 нГн ±5% О
designator L?, comment 33 нГн ±5%  (value not drawn)
Катушка индуктивности с керамическим сердечником; Номиналиная индуктивность: 33 нГн; Добротность, не менее: 35; Резонансная частота, не менее: 3.7 ГГц; Сопротивление обмотки постоянноми току, не более: 1.14 Ом; Допустимый ток обмотки: 120 мА; Диапазон рабочих температур: от -40 до +125 ℃; Упаковка: Катушка и лента; Типоразмер: 0603 (0201); Технология монтажа: SMT; Изготовитель: АО "НПО "ЭРКОН"
footprint КИК-0603_О (Катушка индуктивности с керамическим сердечником типоразмер 0603(0201))
pins: 1, 2

## КИК-0603-39 нГн ±5% О
designator L?, comment 39 нГн ±5%  (value not drawn)
Катушка индуктивности с керамическим сердечником; Номиналиная индуктивность: 39 нГн; Добротность, не менее: 35; Резонансная частота, не менее: 3.45 ГГц; Сопротивление обмотки постоянноми току, не более: 1.55 Ом; Допустимый ток обмотки: 100 мА; Диапазон рабочих температур: от -40 до +125 ℃; Упаковка: Катушка и лента; Типоразмер: 0603 (0201); Технология монтажа: SMT; Изготовитель: АО "НПО "ЭРКОН"
footprint КИК-0603_О (Катушка индуктивности с керамическим сердечником типоразмер 0603(0201))
pins: 1, 2

## КИК-0603-47 нГн ±5% О
designator L?, comment 47 нГн ±5%  (value not drawn)
Катушка индуктивности с керамическим сердечником; Номиналиная индуктивность: 47 нГн; Добротность, не менее: 35; Резонансная частота, не менее: 3.25 ГГц; Сопротивление обмотки постоянноми току, не более: 1.7 Ом; Допустимый ток обмотки: 95 мА; Диапазон рабочих температур: от -40 до +125 ℃; Упаковка: Катушка и лента; Типоразмер: 0603 (0201); Технология монтажа: SMT; Изготовитель: АО "НПО "ЭРКОН"
footprint КИК-0603_О (Катушка индуктивности с керамическим сердечником типоразмер 0603(0201))
pins: 1, 2

## КИК-0603-51 нГн ±5% О
designator L?, comment 51 нГн ±5%  (value not drawn)
Катушка индуктивности с керамическим сердечником; Номиналиная индуктивность: 51 нГн; Добротность, не менее: 35; Резонансная частота, не менее: 3.45 ГГц; Сопротивление обмотки постоянноми току, не более: 1.85 Ом; Допустимый ток обмотки: 90 мА; Диапазон рабочих температур: от -40 до +125 ℃; Упаковка: Катушка и лента; Типоразмер: 0603 (0201); Технология монтажа: SMT; Изготовитель: АО "НПО "ЭРКОН"
footprint КИК-0603_О (Катушка индуктивности с керамическим сердечником типоразмер 0603(0201))
pins: 1, 2


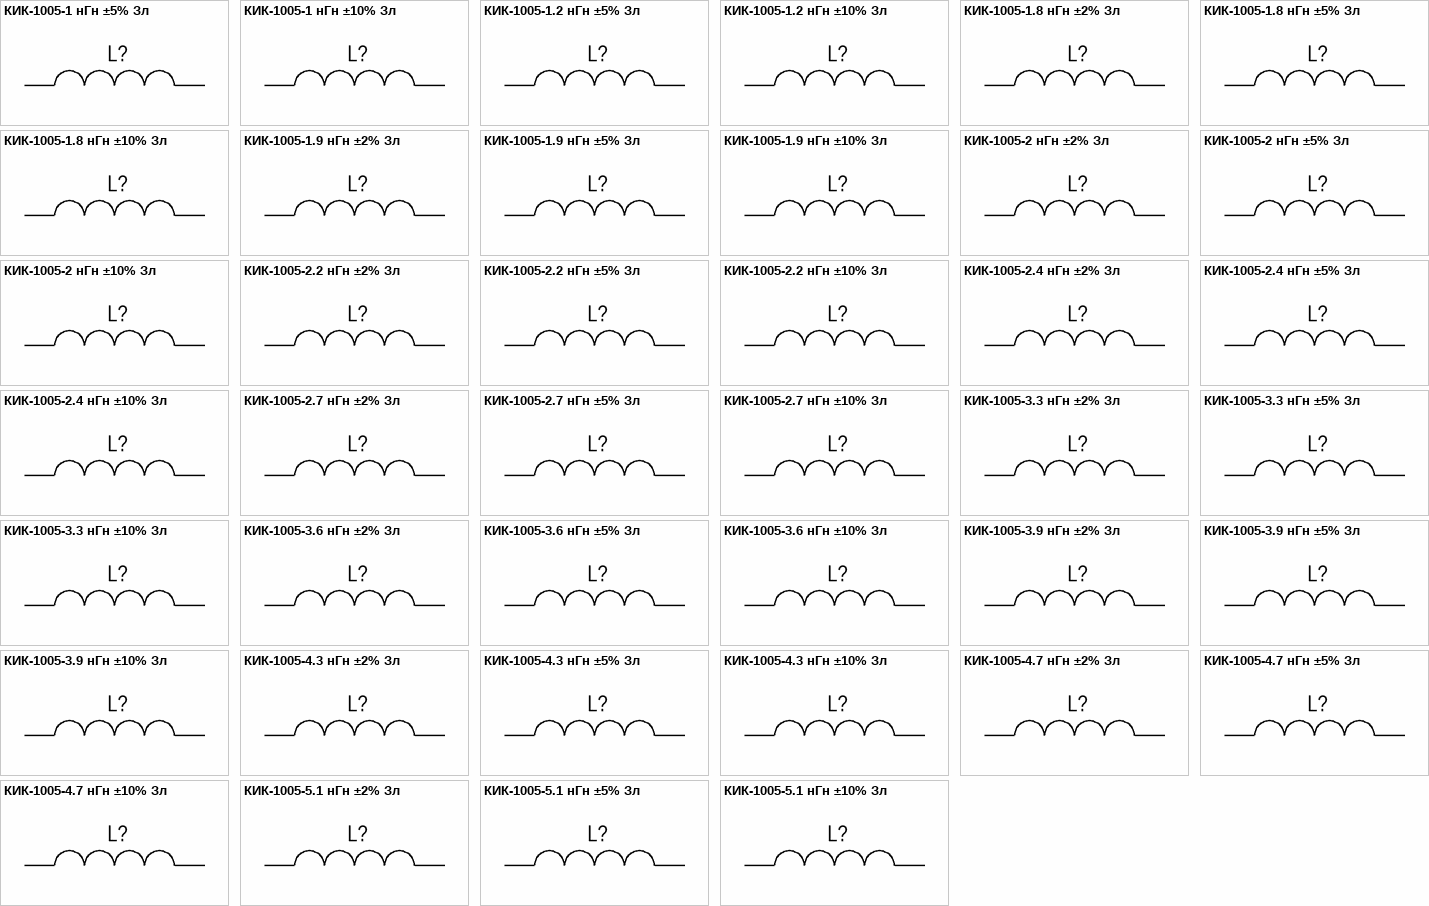
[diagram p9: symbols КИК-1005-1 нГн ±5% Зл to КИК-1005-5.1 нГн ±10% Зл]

## КИК-1005-1 нГн ±5% Зл
designator L?, comment 1 нГн ±5%  (value not drawn)
Катушка индуктивности с керамическим сердечником и золотым покрытием контактных площадок; Номиналиная индуктивность: 1 нГн; Добротность, не менее: 13; Резонансная частота, не менее: 12.70 ГГц; Сопротивление обмотки постоянноми току, не более: 0.045 Ом; Допустимый ток обмотки: 1360 мА; Диапазон рабочих температур: от -60 до +125 ℃; Упаковка: Катушка и лента; Типоразмер: 1005 (0402); Технология монтажа: SMT; Изготовитель: АО "НПО "ЭРКОН"
footprint КИК-1005_Зл (Катушка индуктивности с керамическим сердечником типоразмер 1005(0402))
pins: 1, 2

## КИК-1005-1 нГн ±10% Зл
designator L?, comment 1 нГн ±10%  (value not drawn)
Катушка индуктивности с керамическим сердечником и золотым покрытием контактных площадок; Номиналиная индуктивность: 1 нГн; Добротность, не менее: 13; Резонансная частота, не менее: 12.70 ГГц; Сопротивление обмотки постоянноми току, не более: 0.045 Ом; Допустимый ток обмотки: 1360 мА; Диапазон рабочих температур: от -60 до +125 ℃; Технология монтажа: SMT; Типоразмер: 1005 (0402); Упаковка: Катушка и лента; Изготовитель: АО "НПО "ЭРКОН"
footprint КИК-1005_Зл (Катушка индуктивности с керамическим сердечником типоразмер 1005(0402))
pins: 1, 2

## КИК-1005-1.2 нГн ±5% Зл
designator L?, comment 1.2 нГн ±5%  (value not drawn)
Катушка индуктивности с керамическим сердечником и золотым покрытием контактных площадок; Номиналиная индуктивность: 1.2 нГн; Добротность, не менее: 13; Резонансная частота, не менее: 12.90 ГГц; Сопротивление обмотки постоянноми току, не более: 0.090 Ом; Допустимый ток обмотки: 740 мА; Изготовитель: *АО "НПО "ЭРКОН"; Диапазон рабочих температур: *от -60 до +125 ℃; ипоразмер: 1005 (0402); Технология монтажа: * SMT; Упаковка: Катушка и лента
footprint КИК-1005_Зл (Катушка индуктивности с керамическим сердечником типоразмер 1005(0402))
pins: 1, 2

## КИК-1005-1.2 нГн ±10% Зл
designator L?, comment 1.2 нГн ±10%  (value not drawn)
Катушка индуктивности с керамическим сердечником и золотым покрытием контактных площадок; Номиналиная индуктивность: 1.2 нГн; Добротность, не менее: 13; Резонансная частота, не менее: 12.90 ГГц; Сопротивление обмотки постоянноми току, не более: 0.090 Ом; Допустимый ток обмотки: 740 мА; Изготовитель: АО "НПО "ЭРКОН"; Диапазон рабочих температур: -60 до +125 ℃; Технология монтажа: SMT; Типоразмер: 1005 (0402); Упаковка: Катушка и лента
footprint КИК-1005_Зл (Катушка индуктивности с керамическим сердечником типоразмер 1005(0402))
pins: 1, 2

## КИК-1005-1.8 нГн ±2% Зл
designator L?, comment 1.8 нГн ±2%  (value not drawn)
Катушка индуктивности с керамическим сердечником и золотым покрытием контактных площадок; Номиналиная индуктивность: 1.8 нГн; Добротность, не менее: 13; Резонансная частота, не менее: 12.00 ГГц; Сопротивление обмотки постоянноми току, не более: 0.090 Ом; Допустимый ток обмотки: 1040 мА; Изготовитель: АО "НПО "ЭРКОН"; Диапазон рабочих температур: от -60 до +125 ℃; Технология монтажа: SMT; Типоразмер: 1005 (0402); Упаковка: Катушка и лента
footprint КИК-1005_Зл (Катушка индуктивности с керамическим сердечником типоразмер 1005(0402))
pins: 1, 2

## КИК-1005-1.8 нГн ±5% Зл
designator L?, comment 1.8 нГн ±5%  (value not drawn)
Катушка индуктивности с керамическим сердечником и золотым покрытием контактных площадок; Номиналиная индуктивность: 1.8 нГн; Добротность, не менее: 13; Резонансная частота, не менее: 12.00 ГГц; Сопротивление обмотки постоянноми току, не более: 0.090 Ом; Допустимый ток обмотки: 1040 мА; Изготовитель: АО "НПО "ЭРКОН"; Диапазон рабочих температур: от -60 до +125 ℃; Технология монтажа: SMT; Типоразмер: 1005 (0402); Упаковка: Катушка и лента
footprint КИК-1005_Зл (Катушка индуктивности с керамическим сердечником типоразмер 1005(0402))
pins: 1, 2

## КИК-1005-1.8 нГн ±10% Зл
designator L?, comment 1.8 нГн ±10%  (value not drawn)
Катушка индуктивности с керамическим сердечником и золотым покрытием контактных площадок; Номиналиная индуктивность: 1.8 нГн; Добротность, не менее: 13; Резонансная частота, не менее: 12.00 ГГц; Сопротивление обмотки постоянноми току, не более: 0.090 Ом; Допустимый ток обмотки: 1040 мА; Изготовитель: АО "НПО "ЭРКОН"; Диапазон рабочих температур: от -60 до +125 ℃; Технология монтажа: SMT; Типоразмер: 1005 (0402); Упаковка: Катушка и лента
footprint КИК-1005_Зл (Катушка индуктивности с керамическим сердечником типоразмер 1005(0402))
pins: 1, 2

## КИК-1005-1.9 нГн ±2% Зл
designator L?, comment 1.9 нГн ±2%  (value not drawn)
Катушка индуктивности с керамическим сердечником и золотым покрытием контактных площадок; Номиналиная индуктивность: 1.9 нГн; Добротность, не менее: 13; Резонансная частота, не менее: 11.30 ГГц; Сопротивление обмотки постоянноми току, не более: 0.090 Ом; Допустимый ток обмотки: 1040 мА; Диапазон рабочих температур: от -60 до +125 ℃; Технология монтажа: SMT; Типоразмер: 1005 (0402; Упаковка: Катушка и лента
footprint КИК-1005_Зл (Катушка индуктивности с керамическим сердечником типоразмер 1005(0402))
pins: 1, 2

## КИК-1005-1.9 нГн ±5% Зл
designator L?, comment 1.9 нГн ±5%  (value not drawn)
Катушка индуктивности с керамическим сердечником и золотым покрытием контактных площадок; Номиналиная индуктивность: 1.9 нГн; Добротность, не менее: 13; Резонансная частота, не менее: 11.30 ГГц; Сопротивление обмотки постоянноми току, не более: 0.090 Ом; Допустимый ток обмотки: 1040 мА; Диапазон рабочих температур: от -60 до +125 ℃; Технология монтажа: SMT; Типоразмер: 1005 (0402; Упаковка: Катушка и лента
footprint КИК-1005_Зл (Катушка индуктивности с керамическим сердечником типоразмер 1005(0402))
pins: 1, 2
